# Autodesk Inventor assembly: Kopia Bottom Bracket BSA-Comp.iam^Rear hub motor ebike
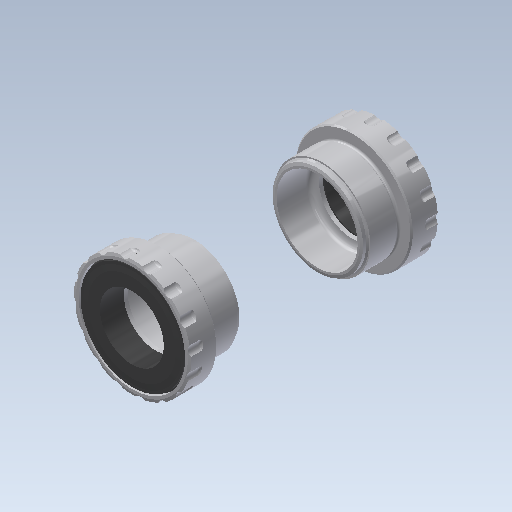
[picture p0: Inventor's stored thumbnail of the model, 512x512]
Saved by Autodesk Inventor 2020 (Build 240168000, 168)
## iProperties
Created: 2017-11
Part Number: Kopia Bottom Bracket BSA-Comp.iam^Rear hub motor ebike
Material: Ogólny
Document SubType Name: Assembly
Designer: Tomasz
Sending System: SolidWorks 2017
Last Author: Tomasz
Last Saved: 2017-11-19
Author: Tomasz
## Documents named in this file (2)
- C:\Users\bruno\Documents\1-Cours-2020-21\1STI2D-2020-21\IT\6. Antivol\Inventor-Antivol\INVENTOR 2018_Steel Hardtail B+\Kopia Bottom Bracket BSA-Comp.iam^Rear hub motor ebike.iam
- C:\Users\bruno\Documents\1-Cours-2020-21\1STI2D-2020-21\IT\6. Antivol\Inventor-Antivol\INVENTOR 2018_Steel Hardtail B+\Kopia Bottom Bracket BSA.iam^Kopia Bottom Bracket BSA-Comp.iam_Rear hub motor ebike.iam
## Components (2 placed, 1 different names)
1. Kopia Bottom Bracket BSA.iam^Kopia Bottom Bracket BSA-Comp.iam_Rear hub motor ebike:1 [sub-assembly]
2. Kopia Bottom Bracket BSA.iam^Kopia Bottom Bracket BSA-Comp.iam_Rear hub motor ebike:2 [sub-assembly]
